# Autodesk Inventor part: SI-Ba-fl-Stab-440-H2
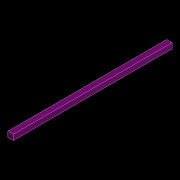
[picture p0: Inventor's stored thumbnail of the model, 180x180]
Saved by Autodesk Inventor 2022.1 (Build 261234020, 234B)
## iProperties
Part Number: SI-Ba-fl-Stab-440-H2
Material: Allgemein
Document SubType Name: Modellieren
Designer: joachim
Appearance: Vorgabe
Author: joachim
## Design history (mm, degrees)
sketch "Skizze1"
  geometry: L1 (0, 0)-(15, 0); L2 (15, 0)-(15, 15); L3 (15, 15)-(0, 15); L4 (0, 15)-(0, 0)
  constraints: 8 end point, 2 parallel, 1 horizontal, 1 perpendicular
  dimensions: "d0" = 15 distance of L3.end L2.end; "d1" = 15 distance of L2.end L1.end
extrude "Extrusion1" new body sketch "Skizze1" distance "d2" = 440; taper "d3" = 0 deg
node "Volumenkörper1"
node "Volumenkörper"
node "Flächenkörper"
